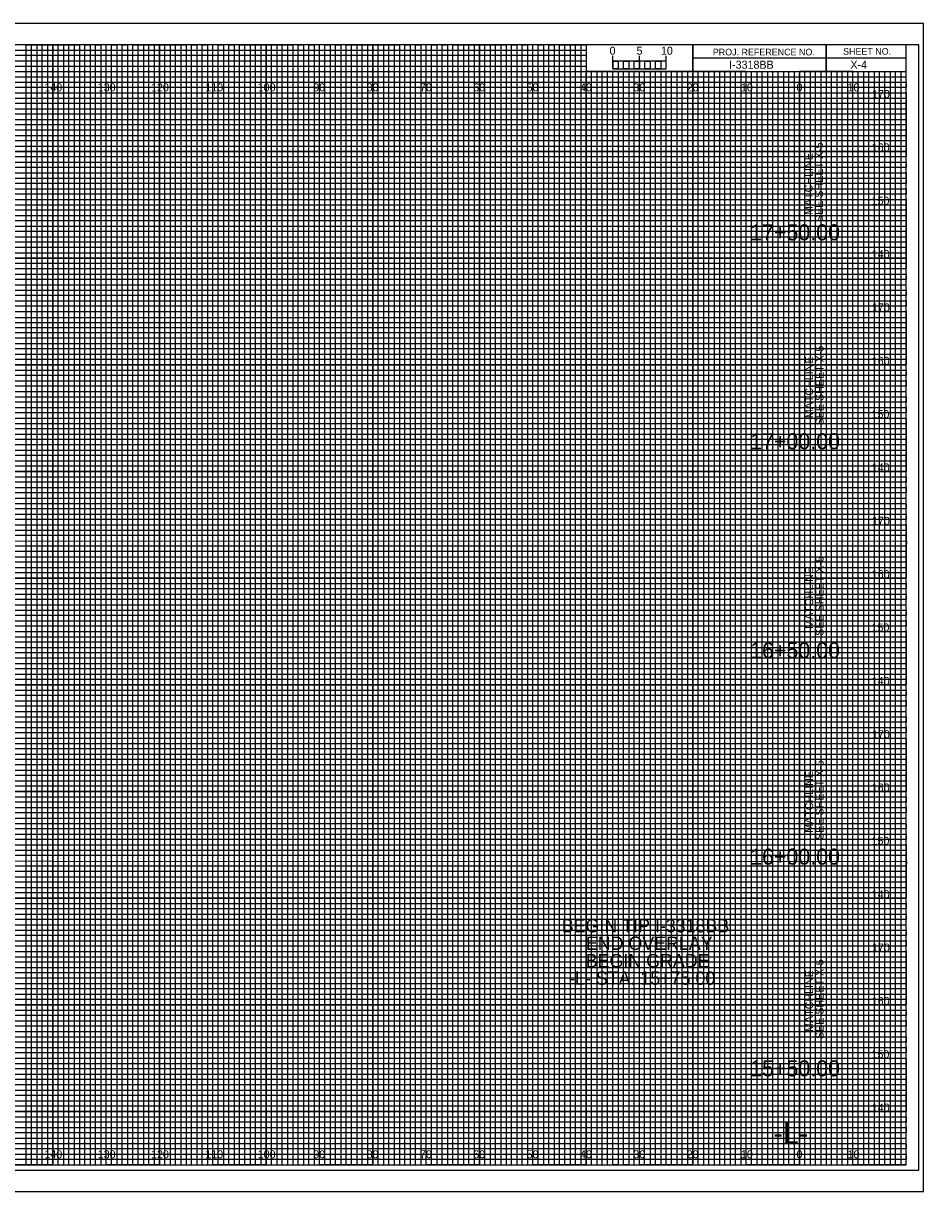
# Model space of a CAD drawing. Extents: x -13 to 323, y -5 to 214.
# Drawn here: x 154.5 to 323.3, y -5 to 214 of the extents above; entities that cross this region are included whole.
import ezdxf

# ---------------------------------------------------------------- set-up
doc = ezdxf.new("R2010")
doc.units = 0
for name, color, linetype in [('Exist Cross Section Cell', 7, 'Continuous'), ('Exist XS Center Line Elevation Label', 7, 'Continuous'), ('Exist XS Ground Line', 7, 'Continuous'), ('Matchline', 7, 'Continuous'), ('Prop CMT Pvmt Course 1', 7, 'Continuous'), ('Prop CMT Pvmt Course 1 Wedge', 7, 'Continuous'), ('Prop CMT Pvmt Course 2', 7, 'Continuous'), ('Prop CMT Pvmt Surface', 7, 'Continuous'), ('Prop CMT Pvmt Surface Overlay', 7, 'Continuous'), ('Prop CMT Pvmt Surface Shoulder', 7, 'Continuous'), ('Prop CMT Shld Paved Course 1', 7, 'Continuous'), ('Prop CMT Shld Paved Course 2', 7, 'Continuous'), ('Prop CMT Shld Paved Course 3', 7, 'Continuous'), ('Prop CMT Slope Grass', 7, 'Continuous'), ('Prop CMT Subgrade Earthwork', 7, 'Continuous'), ('Prop XS Vertical Lines Alignments', 7, 'Continuous'), ('Scratch_Level_0', 7, 'Continuous'), ('Scratch_Level_1', 7, 'Continuous'), ('Scratch_Level_9', 7, 'Continuous')]:
    doc.layers.add(name, color=color, linetype=linetype)

msp = doc.modelspace()

# ---------------------------------------------------------------- linework, layer by layer
at = {"layer": 'Exist XS Center Line Elevation Label'}
for p, q in [((0, 209), (260, 209)), ((260, 209), (260, 207.98)), ((260, 207.98), (0, 207.98)), ((0, 207), (260, 207)), ((260, 205.89), (0, 205.89)), ((260, 207), (260, 205.89)), ((0, 204), (320, 204))]:
    msp.add_line(p, q, dxfattribs=at)
for points in [[(0, 203), (270, 203), (320, 203), (320, 202), (0, 202)], [(0, 201), (320, 201), (320, 199), (0, 199)], [(0, 198), (320, 198), (320, 197), (0, 196.98)], [(0, 196), (320, 196), (320, 194), (0, 194)], [(0, 193), (320, 193), (320, 192), (0, 192)], [(0, 191), (320, 191), (320, 189), (0, 189)], [(0, 188), (320, 188), (320, 187), (0, 187)], [(0, 186), (320, 186), (320, 184), (0, 184)], [(0, 183), (320, 183), (320, 182), (0, 182)], [(0, 181), (320, 181), (320, 179), (0, 179)], [(0, 178), (320, 178), (320, 177), (0, 177)], [(0, 176), (320, 176), (320, 173.95), (320, 173), (320, 172), (0, 172)], [(0, 174), (320, 174), (320, 173), (0, 173)], [(0, 171), (320, 171), (320, 169), (0, 169.03)], [(0, 169.03), (320, 169), (320, 168), (0, 168)], [(0, 167), (320, 167), (320, 166), (0, 166)], [(0, 164), (320, 164), (320, 163), (0, 163)], [(0, 162), (320, 162), (320, 161), (0, 161)], [(-0.07, 158.89), (320, 158.89), (320, 157.88), (-0.07, 157.88)], [(0, 157), (320, 157), (320, 156), (0, 156)], [(0, 154), (320, 154), (320, 153), (0, 153)], [(0, 152), (320, 152), (320, 151), (0, 151)], [(0, 149), (320, 149), (320, 148), (0, 148)], [(0, 147), (320, 147), (320, 146), (0, 146)], [(0, 144), (320, 144), (320, 143), (0, 143)], [(0, 142), (320, 142), (320, 141), (0, 141)], [(0, 139), (320, 139), (319.99, 137.98), (0, 138)], [(0, 137), (320, 137), (320, 136), (0, 136)], [(0, 134), (320, 134), (320, 133), (0, 133)], [(0, 132), (320, 132), (320, 131), (0, 131)], [(0, 129), (320, 129), (320, 128), (0, 128)], [(0, 127), (320, 127), (320, 126), (0, 126)], [(0, 124), (320, 124), (320, 123), (0, 123)], [(0, 122), (320, 122), (320, 121), (0, 121)], [(0, 119), (320, 119), (320, 118), (0, 118)], [(0, 116.99), (320.07, 116.91), (320, 116), (0, 116)], [(0, 114), (320, 114), (320, 113), (0, 113)], [(0, 112), (320, 112), (320, 111), (0, 111)], [(0, 109), (320, 109), (320, 108), (0, 108)], [(0, 107), (320, 107), (320, 106), (0, 106)], [(0, 104), (320, 104), (320, 103), (0, 103)], [(0, 102), (320, 102), (320, 101), (0, 101)], [(0, 99), (320, 99), (320, 98), (0, 98)], [(0, 97), (320, 97), (320, 96), (0, 96)], [(0, 94), (320, 94), (320, 93), (0, 93)], [(0, 92), (320, 92), (320, 91), (0, 91)], [(0, 89), (320, 89), (320, 88), (0, 88)], [(0, 87), (320, 87), (320, 86), (0, 86)], [(0, 84), (320, 84), (320, 83), (0, 83)], [(0, 82), (320, 82), (320, 81), (0, 81)], [(0, 79), (320, 79), (319.99, 77.98), (0, 78)], [(0, 77), (320, 77), (320, 76), (0, 76)], [(0, 74), (320, 74), (320, 73), (0, 73)], [(0, 72), (320, 72), (320, 71), (0, 71)], [(0, 69), (320, 69), (320, 68), (0, 68)], [(0, 67), (320, 67), (320, 66), (0, 66)], [(0, 64), (320, 64), (320, 63), (0, 63)], [(0, 62), (320, 62), (320, 61), (0, 61)], [(0, 59), (320, 59), (320, 58), (0, 58)], [(0, 56.99), (320.07, 56.91), (320, 56), (0, 56)], [(0, 54), (320, 54), (320, 53), (0, 53)], [(0, 52), (320, 52), (320, 51), (0, 51)], [(0, 49), (320, 49), (320, 48), (0, 48)], [(0, 47), (320, 47), (320, 46), (0, 46)], [(0, 44), (320, 44), (320, 43), (0, 43)], [(0, 42), (320, 42), (320, 41), (0, 41)], [(0, 39), (320, 39), (320, 38), (0, 38)], [(0, 37), (320, 37), (320, 36), (0, 36)], [(0, 34), (320, 34), (320, 33), (0, 33)], [(0, 32), (320, 32), (320, 31), (0, 31)], [(0, 29), (320, 29), (320, 28), (0, 28)], [(0, 27), (320, 27), (320, 26), (0, 26)], [(0, 24), (320, 24), (320, 23), (0, 23)], [(0, 22), (320, 22), (320, 21), (0, 21)], [(0, 19), (320, 19), (320, 18), (0, 18)], [(0, 17), (320, 17), (320, 16), (0, 16)], [(0, 14), (320, 14), (320, 13), (0, 13)], [(0, 12), (320, 12), (320, 11), (0, 11)], [(0, 9), (320, 9), (320, 8), (0, 8)], [(0, 7), (320, 7), (320, 6), (0, 6)], [(0, 4), (320, 4), (320, 3), (0, 3)], [(0, 2), (320, 2), (320, 1), (0, 1)]]:
    msp.add_lwpolyline(points, dxfattribs=at)
at = {"layer": 'Exist XS Ground Line'}
for points in [[(145, 0), (155, 0), (155, 210), (165, 210), (165, 0), (175, 0), (175, 210), (185, 210), (185, 0), (195, 0), (195, 210), (205, 210), (205, 0), (215, 0), (215, 210), (225, 210), (225, 0), (235, 0), (235, 210), (245, 210), (245, 0), (255, 0), (255, 210), (259.93, 210), (260, 210), (260, 205), (264.99, 205), (264.99, 0), (275, 0), (275, 205), (285, 205), (285, 0), (295, 0), (295, 205), (305, 205), (305, 0), (315, 0), (315, 205)], [(0, 205), (275, 205)], [(0, 185), (320, 185), (320, 195), (0, 195)], [(0, 165), (320, 165), (320, 175), (0, 175)], [(0, 145), (320, 145), (320, 155), (0, 155)], [(0, 125), (320, 125), (320, 135), (0, 135)], [(0, 105), (320, 105), (320, 115), (0, 115)], [(0, 85), (320, 85), (320, 95), (0, 95)], [(0, 65), (320, 65), (320, 75), (0, 75)], [(0, 45), (320, 45), (320, 55), (0, 55)], [(0, 25), (320, 25), (320, 35), (0, 35)], [(0, 5), (320, 5), (320, 15), (0, 15)]]:
    msp.add_lwpolyline(points, dxfattribs=at)
at = {"layer": 'Prop CMT Pvmt Course 1'}
for p, q in [((323.3, 214), (-13.4, 214)), ((-13.4, -5), (323.3, -5))]:
    msp.add_line(p, q, dxfattribs=at)
at = {"layer": 'Prop CMT Pvmt Surface'}
msp.add_lwpolyline([(-13.4, -5), (323.3, -5), (323.3, 214), (-13.4, 214)], close=True, dxfattribs=at)
at = {"layer": 'Prop CMT Pvmt Surface Shoulder'}
for p, q in [((160, 0), (160, 210)), ((170, 0), (170, 210)), ((180, 0), (180, 210)), ((190, 0), (190, 210)), ((200, 0), (200, 210)), ((210, 0), (210, 210)), ((220, 0), (220, 210)), ((230, 0), (230, 210)), ((240, 0), (240, 210)), ((250, 0), (250, 210)), ((260, 0), (260, 204.69)), ((270, 0), (270, 204.69)), ((280, 0), (280, 204.69)), ((290, 0), (290, 204.69)), ((300, 0), (300, 204.69)), ((310, 0), (310, 204.69)), ((0, 200), (320, 200)), ((0, 190), (320, 190)), ((0, 180), (320, 180)), ((0, 170), (320, 170)), ((0, 160), (320, 160)), ((0, 150), (320, 150)), ((0, 140), (320, 140)), ((0, 130), (320, 130)), ((0, 120), (320, 120)), ((0, 110), (320, 110)), ((0, 100), (320, 100)), ((0, 90), (320, 90)), ((0, 80), (320, 80)), ((0, 70), (320, 70)), ((0, 60), (320, 60)), ((0, 50), (320, 50)), ((0, 40), (320, 40)), ((0, 30), (320, 30)), ((0, 20), (320, 20)), ((0, 10), (320, 10))]:
    msp.add_line(p, q, dxfattribs=at)
at = {"layer": 'Prop CMT Shld Paved Course 1'}
for p, q in [((305, 210), (305, 205)), ((305, 205), (305, 210)), ((280, 207.5), (280, 205)), ((320, 207.49), (280, 207.49)), ((280, 205), (320, 205))]:
    msp.add_line(p, q, dxfattribs=at)
for points in [[(320, 210), (0, 210), (0, 0), (320, 0)], [(280, 210), (260, 210), (260, 205.03), (280, 205.03)], [(320, 210), (280, 210), (280, 205), (320, 205)]]:
    msp.add_lwpolyline(points, close=True, dxfattribs=at)
at = {"layer": 'Prop CMT Shld Paved Course 2'}
for p, q in [((267, 205), (266.01, 205)), ((266.01, 205), (266.01, 0)), ((267, 0), (267, 205)), ((269, 205), (268, 205)), ((268, 205), (268, 0)), ((269, 0), (269, 205)), ((266.01, 0), (265, 0)), ((268, 0), (267, 0))]:
    msp.add_line(p, q, dxfattribs=at)
for points in [[(155, 0), (156, 0), (156, 210), (157, 210), (157, 0)], [(157, 0), (158, 0), (158, 210), (159, 210), (159, 0)], [(160, 0), (161, 0), (161, 210), (162, 210), (162, 0)], [(162, 0), (163, 0), (163, 210), (164, 210), (164, 0)], [(165, 0), (166, 0), (166, 210), (167, 210), (167, 0)], [(167, 0), (168, 0), (168, 210), (169, 210), (169, 0)], [(170, 0), (171, 0), (171, 210), (172, 210), (172, 0)], [(172, 0), (173, 0), (173, 210), (174, 210), (174, 0)], [(175, 0), (176, 0), (176, 210), (177, 210), (177, 0)], [(177, 0), (178, 0), (178, 210), (179, 210), (179, 0)], [(180, 0), (181, 0), (181, 210), (182, 210), (182, 0)], [(182, 0), (183, 0), (183, 210), (184, 210), (184, 0)], [(185, 0), (186, 0), (186, 210), (187, 210), (187, 0)], [(187, 0), (188, 0), (188, 210), (189, 210), (189, 0)], [(190, 0), (191, 0), (191, 210), (192, 210), (192, 0)], [(192, 0), (193, 0), (193, 210), (194, 210), (194, 0)], [(195, 0), (196, 0), (196, 210), (197, 210), (197, 0)], [(197, 0), (198, 0), (198, 210), (199, 210), (199, 0)], [(200, 0), (201, 0), (201, 210), (202, 210), (202, 0)], [(202, 0), (203, 0), (203, 210), (204, 210), (204, 0)], [(205, 0), (206, 0), (206, 210), (207, 210), (207, 0)], [(207, 0), (208, 0), (208, 210), (209, 210), (209, 0)], [(210, 0), (211, 0), (211, 210), (212, 210), (212, 0)], [(212, 0), (213, 0), (213, 210), (214, 210), (214, 0)], [(215, 0), (216, 0), (216, 210), (217, 210), (217, 0)], [(217, 0), (218, 0), (218, 210), (219, 210), (219, 0)], [(220, 0), (221, 0), (221, 210), (222, 210), (222, 0)], [(222, 0), (223, 0), (223, 210), (224, 210), (224, 0)], [(225, 0), (226, 0), (226, 210), (227, 210), (227, 0)], [(227, 0), (228, 0), (228, 210), (229, 210), (229, 0)], [(230, 0), (231, 0), (231, 210), (232, 210), (232, 0)], [(232, 0), (233, 0), (233, 210), (234, 210), (234, 0)], [(235, 0), (236, 0), (236, 210), (237, 210), (237, 0)], [(237, 0), (238, 0), (238, 210), (239, 210), (239, 0)], [(240, 0), (241, 0), (241, 210), (242, 210), (242, 0)], [(242, 0), (243, 0), (243, 210), (244, 210), (244, 0)], [(245, 0), (246, 0), (246, 210), (247, 210), (247, 0)], [(247, 0), (248, 0), (248, 210), (249, 210), (249, 0)], [(250, 0), (251, 0), (251, 210), (252, 210), (252, 0)], [(252, 0), (253, 0), (253, 210), (254, 210), (254, 0)], [(255, 0), (256, 0), (256, 210), (257, 210), (257, 0)], [(257, 0), (258, 0), (258, 210), (259, 210), (259, 0)], [(260, 0), (261, 0), (261, 205), (262.02, 205), (262.02, 0)], [(262, 0), (263, 0), (263, 205), (263.99, 205), (263.99, 0)], [(270, 0), (270.98, 0), (270.98, 205), (272, 205), (272, 0)], [(272, 0), (273, 0), (273, 205), (274.05, 205), (274.05, 0)], [(275, 0), (276, 0), (276, 205), (277, 205), (277, 0)], [(277, 0), (278, 0), (278, 205), (279, 205), (279, 0)], [(280, 0), (281, 0), (281, 205), (282, 205), (282, 0)], [(282, 0), (283, 0), (283, 205), (284, 205), (284, 0)], [(285, 0), (286, 0), (286, 205), (287, 205), (287, 0)], [(287, 0), (288, 0), (288, 205), (289, 205), (289, 0)], [(290, 0), (291, 0), (291, 205), (292, 205), (292, 0)], [(292, 0), (293, 0), (293, 205), (294, 205), (294, 0)], [(295, 0), (296, 0), (296, 205), (297, 205), (297, 0)], [(297, 0), (298, 0), (298, 205), (299, 205), (299, 0)], [(300, 0), (301, 0), (301, 205), (302, 205), (302, 0)], [(302, 0), (303, 0), (303, 205), (304, 205), (304, 0)], [(305, 0), (306, 0), (306, 205), (307, 205), (307, 0)], [(307, 0), (308, 0), (308, 205), (309, 205), (309, 0)], [(310, 0), (311, 0), (311, 205), (312, 205), (312, 0)], [(312, 0), (313, 0), (313, 205), (314, 205), (314, 0)], [(315, 0), (316, 0), (316, 205), (317, 205), (317, 0)], [(317, 0), (318, 0), (318, 205), (319, 205), (319, 0)]]:
    msp.add_lwpolyline(points, dxfattribs=at)
at = {"layer": 'Prop CMT Subgrade Earthwork'}
for p, q in [((265, 205.49), (265, 207.9)), ((265, 206.9), (265, 207.9)), ((270, 205.49), (270, 207.9)), ((275, 205.49), (275, 207.9)), ((275, 206.9), (275, 207.9))]:
    msp.add_line(p, q, dxfattribs=at)
for points in [[(275, 206.9), (265, 206.9), (265, 205.49), (275, 205.49)], [(265, 206.9), (266, 206.9), (266, 205.49), (265, 205.49)], [(267, 206.9), (268, 206.9), (268, 205.49), (267, 205.49)], [(269, 206.9), (270, 206.9), (270, 205.49), (269, 205.49)], [(271, 206.9), (272, 206.9), (272, 205.49), (271, 205.49)], [(273, 206.9), (274, 206.9), (274, 205.49), (273, 205.49)]]:
    msp.add_lwpolyline(points, close=True, dxfattribs=at)
at = {"layer": 'Prop XS Vertical Lines Alignments'}
msp.add_lwpolyline([(-10.8, -1), (322.4, -1), (322.4, 210), (-10.8, 210)], close=True, dxfattribs=at)
at = {"layer": 'Scratch_Level_9'}
for p, q in [((170, 210), (160, 210)), ((160, 210), (160, 0)), ((170, 0), (170, 210)), ((190, 210), (180, 210)), ((180, 210), (180, 0)), ((190, 0), (190, 210)), ((210, 210), (200, 210)), ((200, 210), (200, 0)), ((210, 0), (210, 210)), ((230, 210), (220, 210)), ((220, 210), (220, 0)), ((230, 0), (230, 210)), ((250, 210), (240, 210)), ((240, 210), (240, 0)), ((250, 0), (250, 210)), ((260, 210), (260, 0)), ((270, 0), (270, 205)), ((290, 205), (280, 205)), ((280, 205), (280, 0)), ((290, 0), (290, 205)), ((310, 205), (300, 205)), ((300, 205), (300, 0)), ((310, 0), (310, 205)), ((160, 0), (150, 0)), ((180, 0), (170, 0)), ((200, 0), (190, 0)), ((220, 0), (210, 0)), ((240, 0), (230, 0)), ((260, 0), (250, 0)), ((280, 0), (270, 0)), ((300, 0), (290, 0)), ((320, 0), (310, 0)), ((320, 0), (320, 0))]:
    msp.add_line(p, q, dxfattribs=at)
for points in [[(0, 200), (320, 200), (320, 190), (0, 190)], [(0, 180), (320, 180), (320, 170), (0, 170)], [(0, 160), (320, 160), (320, 150), (0, 150)], [(0, 140), (320, 140), (320, 130), (0, 130)], [(0, 120), (320, 120), (320, 110), (0, 110)], [(0, 100), (320, 100), (320, 90), (0, 90)], [(0, 80), (320, 80), (320, 70), (0, 70)], [(0, 60), (320, 60), (320, 50), (0, 50)], [(0, 40), (320, 40), (320, 30), (0, 30)], [(0, 20), (320, 20), (320, 10), (0, 10)]]:
    msp.add_lwpolyline(points, dxfattribs=at)

# ---------------------------------------------------------------- texts
at = {"layer": 'Exist Cross Section Cell'}
for s, p in [('140', (158.44, 201.25)), ('130', (168.44, 201.25)), ('120', (178.44, 201.25)), ('110', (188.62, 201.25)), ('100', (198.44, 201.25)), ('90', (208.86, 201.25)), ('80', (218.86, 201.25)), ('70', (228.86, 201.25)), ('60', (238.86, 201.25)), ('50', (248.86, 201.25)), ('40', (258.86, 201.25)), ('30', (268.86, 201.25)), ('20', (278.86, 201.25)), ('10', (289.04, 201.25)), ('0', (299.45, 201.25)), ('0', (299.45, 201.25)), ('10', (309.04, 201.25)), ('140', (158.44, 1.25)), ('130', (168.44, 1.25)), ('120', (178.44, 1.25)), ('110', (188.62, 1.25)), ('100', (198.44, 1.25)), ('90', (208.86, 1.25)), ('80', (218.86, 1.25)), ('70', (228.86, 1.25)), ('60', (238.86, 1.25)), ('50', (248.86, 1.25)), ('40', (258.86, 1.25)), ('30', (268.86, 1.25)), ('20', (278.86, 1.25)), ('10', (289.04, 1.25)), ('0', (299.45, 1.25)), ('0', (299.45, 1.25)), ('10', (309.04, 1.25))]:
    msp.add_text(s, height=1.5, dxfattribs=at).set_placement(p)
at = {"layer": 'Matchline'}
msp.add_text('I-3318BB', height=1.5, dxfattribs=at).set_placement((286.82, 205.5))
at = {"layer": 'Prop CMT Pvmt Course 1 Wedge'}
for s, p in [('BEGIN TIP I-3318BB', (255.45, 43.6)), ('END OVERLAY ', (259.96, 40.32)), ('BEGIN GRADE', (259.94, 37.04)), ('-L- STA. 15+75.00', (256.82, 33.77))]:
    msp.add_text(s, height=2.5, dxfattribs=at).set_placement(p)
at = {"layer": 'Prop CMT Pvmt Course 2'}
for s, p in [('170', (313.61, 200)), ('160', (313.57, 190)), ('150', (313.52, 180)), ('140', (313.57, 170)), ('170', (313.61, 160)), ('160', (313.57, 150)), ('150', (313.52, 140)), ('140', (313.57, 130)), ('170', (313.61, 120)), ('160', (313.57, 110)), ('150', (313.52, 100)), ('140', (313.57, 90)), ('170', (313.61, 80)), ('160', (313.57, 70)), ('150', (313.52, 60)), ('140', (313.57, 50)), ('170', (313.61, 40)), ('160', (313.57, 30)), ('150', (313.52, 20)), ('140', (313.57, 10))]:
    msp.add_text(s, height=1.5, dxfattribs=at).set_placement(p)
at = {"layer": 'Prop CMT Pvmt Surface Overlay'}
for s, p in [('17+50.00', (290.77, 173.33)), ('17+00.00', (290.77, 134.16)), ('16+50.00', (290.77, 94.97)), ('16+00.00', (290.77, 56.3)), ('15+50.00', (290.77, 16.61))]:
    msp.add_text(s, height=3, dxfattribs=at).set_placement(p)
at = {"layer": 'Prop CMT Shld Paved Course 1'}
for s, p in [('PROJ. REFERENCE NO.', (283.77, 207.99)), ('SHEET NO.', (308.19, 208.12))]:
    msp.add_text(s, height=1.25, dxfattribs=at).set_placement(p)
at = {"layer": 'Prop CMT Shld Paved Course 3'}
for s, p in [('SEE SHEET X-5', (304.44, 176.75)), (' MATCHLINE ', (302.48, 177.52)), ('SEE SHEET X-5', (304.54, 138.64)), (' MATCHLINE ', (302.58, 139.42)), ('SEE SHEET X-5', (304.54, 99.19)), (' MATCHLINE ', (302.58, 99.96)), ('SEE SHEET X-5', (304.54, 60.94)), (' MATCHLINE ', (302.58, 61.71)), ('SEE SHEET X-5', (304.54, 23.61)), (' MATCHLINE ', (302.58, 24.38))]:
    msp.add_text(s, height=1.5, rotation=90, dxfattribs=at).set_placement(p)
at = {"layer": 'Prop CMT Slope Grass'}
msp.add_text('X-4', height=1.5, dxfattribs=at).set_placement((309.57, 205.5))
at = {"layer": 'Prop CMT Subgrade Earthwork'}
msp.add_text('0', height=1.5, dxfattribs=at).set_placement((264.41, 208.12))
at = {"layer": 'Scratch_Level_0'}
msp.add_text('-L-', height=4, dxfattribs=at).set_placement((295.12, 4))
at = {"layer": 'Scratch_Level_1'}
for s, p in [('5', (269.47, 208.12)), ('10', (274.04, 208.12))]:
    msp.add_text(s, height=1.5, dxfattribs=at).set_placement(p)

doc.saveas('drawing.dxf')
